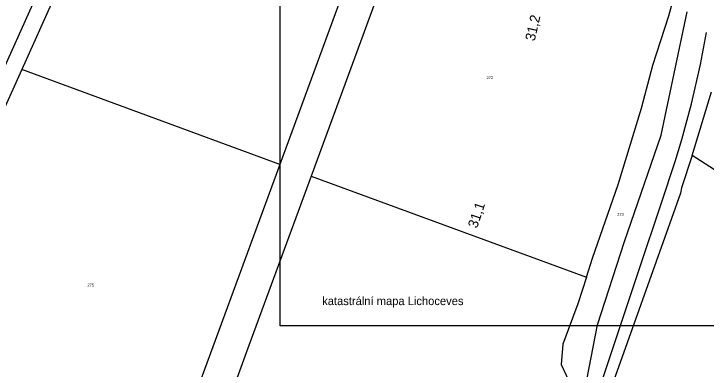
# Model space of a CAD drawing. Extents: x -752343 to -750336, y -1035826 to -1033329.
# Drawn here: x -752107 to -751691.8, y -1034585.7 to -1034372.6 of the extents above; entities that cross this region are included whole.
import ezdxf

# ---------------------------------------------------------------- set-up
doc = ezdxf.new("R2010")
doc.units = 0
for name, color, linetype in [('KN_HRANICE', 7, 'Continuous'), ('KN_PARCELY', 7, 'Continuous'), ('LEGENDA', 7, 'Continuous'), ('Vrstva 1', 7, 'Continuous'), ('Vrstva 7', 7, 'Continuous')]:
    doc.layers.add(name, color=color, linetype=linetype)

msp = doc.modelspace()

# ---------------------------------------------------------------- linework, layer by layer
at = {"layer": 'KN_HRANICE'}
for p, q in [((-752028.02, -1034241.47), (-752102.26, -1034405.99)), ((-752125.54, -1034433.28), (-752081.62, -1034335.95)), ((-751714.12, -1034373.75), (-751704.51, -1034338.37)), ((-751907.9, -1034355.29), (-751947.46, -1034462.91)), ((-751889.68, -1034363.68), (-751928.71, -1034469.86)), ((-751723.83, -1034403.27), (-751714.12, -1034373.75)), ((-751718.7, -1034445.42), (-751703.26, -1034371.46)), ((-751730.55, -1034429.15), (-751723.83, -1034403.27)), ((-752102.26, -1034405.99), (-752143.42, -1034497.22)), ((-751947.46, -1034462.91), (-752102.26, -1034405.99)), ((-751700.27, -1034457.61), (-751688.64, -1034419.35)), ((-751744.5, -1034474.87), (-751730.55, -1034429.15)), ((-751740.73, -1034509.12), (-751718.7, -1034445.42)), ((-751700.27, -1034457.61), (-751706.56, -1034477.02)), ((-751617.15, -1034510.28), (-751700.27, -1034457.61)), ((-751947.46, -1034462.91), (-752016.36, -1034650.31)), ((-751928.71, -1034469.86), (-751966.06, -1034571.46)), ((-751928.71, -1034469.86), (-751763.64, -1034530.57)), ((-751759.95, -1034519.14), (-751744.5, -1034474.87)), ((-751706.56, -1034477.02), (-751707.12, -1034480.15)), ((-751707.12, -1034480.15), (-751712.49, -1034495.37)), ((-751712.49, -1034495.37), (-751784.1, -1034695.17)), ((-751756.87, -1034559.02), (-751740.73, -1034509.12)), ((-751763.64, -1034530.57), (-751759.95, -1034519.14)), ((-751763.64, -1034530.57), (-751768.8, -1034546.56)), ((-751768.8, -1034546.56), (-751777.75, -1034570.76)), ((-751763.32, -1034591.98), (-751756.87, -1034559.02)), ((-751966.06, -1034571.46), (-752003.42, -1034673.07)), ((-751777.75, -1034570.76), (-751778.71, -1034582.87)), ((-751778.71, -1034582.87), (-751767.03, -1034607.65))]:
    msp.add_line(p, q, dxfattribs=at)
at = {"layer": 'LEGENDA'}
msp.add_lwpolyline([(-751353.18, -1034559.75), (-751947.18, -1034559.75), (-751947.18, -1034139.75), (-751353.18, -1034139.75)], close=True, dxfattribs=at)
at = {"layer": 'Vrstva 1'}
msp.add_lwpolyline([(-751897.2, -1035021.76), (-751890.47, -1035001.59), (-751883.84, -1034981.7), (-751874.62, -1034954.06), (-751858.96, -1034907.12), (-751843.11, -1034859.56), (-751829.15, -1034817.6), (-751814.87, -1034774.82), (-751799.67, -1034729.27), (-751795.49, -1034716.76), (-751783.99, -1034682.32), (-751780.52, -1034671.94), (-751765.77, -1034627.71), (-751764.06, -1034622.57), (-751748.27, -1034575.09), (-751731.67, -1034525.23), (-751718.8, -1034486.61), (-751710.46, -1034461.22), (-751706.41, -1034448.02), (-751700.56, -1034426.56), (-751695.18, -1034403.05), (-751691.59, -1034383.71)], dxfattribs=at)

# ---------------------------------------------------------------- texts
at = {"layer": 'KN_PARCELY'}
for s, p in [('272', (-751823.48, -1034411.71)), ('273', (-751745.13, -1034493.69)), ('275', (-752062.86, -1034536.12))]:
    msp.add_text(s, height=1.7, dxfattribs=at).set_placement(p)
at = {"layer": 'LEGENDA'}
msp.add_text('katastrální mapa Lichoceves', height=5, dxfattribs=at).set_placement((-751922.05, -1034547.26))
at = {"layer": 'Vrstva 7'}
for s, rotation, p in [('31,2', 77.129, (-751794.6, -1034389.23)), ('31,1', 71.5844, (-751829.19, -1034501.56))]:
    msp.add_text(s, height=6, rotation=rotation, dxfattribs=at).set_placement(p)

doc.saveas('drawing.dxf')
